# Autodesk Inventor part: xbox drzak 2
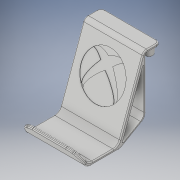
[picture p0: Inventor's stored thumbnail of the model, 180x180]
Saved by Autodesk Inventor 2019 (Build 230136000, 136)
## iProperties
Created: 2022-08
Part Number: xbox drzak 2
Material: Generico
Document SubType Name: Modeling
Designer: holat
Density: 1 g/cm^3
Appearance: Default
Author: holat
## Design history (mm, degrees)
sketch "Náčrt1"
  geometry: L1 (0, 0)-(0, -30); L2 (0, -30)-(70, -55.478); L3 (70, -55.478)-(70, -72.478); L4 (0, 0)-(12.99, 7.5)
  constraints: 8 end point, 1 parallel, 1 vertical
  dimensions: "d0" = 30 distance of L1.start L1.end; "d16" = 17 distance of L2.end L3.end; "d17" = 110 deg angle of L3 L2; "d18" = 120 deg angle of L1 L4; "d26" = 15 distance of L1.start L4.end; "d39" = 70 distance between parallel lines of L1 L3
feature "VysunutíDoPlochy1" sketch "Náčrt1" dims "d1" = 60, "d2" = 0
feature "Zesílit1" dims "d3" = 3, "d4" = 3
sketch "Náčrt2"
  geometry: L1 (0, 0)-(0, 14.899) reference; L2 (60, 14.899)-(60, 0) reference; L3 (0, 14.899)-(60, 14.899) reference; C1 r 4.5 at (54, 5.899); C2 r 4.5 at (6, 5.899); 1 further point
  constraints: 2 centre point
  dimensions: "d5" = 9 diameter of C1; "d6" = 9 diameter of C2 (= d5); "d7" = 48 distance of C2.centre C1.centre; "d10" = 6 distance from line of L2 C1.centre; "d11" = 6 distance from line of L1 C2.centre; "d15" = 9 distance from line of C1.centre L3
extrude "Vysunutí1" join sketch "Náčrt2" distance "d12" = 8; taper "d13" = 0 deg
sketch "Náčrt4"
  geometry: L1 (17, 3)-(42.478, -67) reference; L2 (0, 3)-(17, 3) reference; L3 (0, 3)-(0, 0) reference; L4 (0, 0)-(14.899, 0) reference; L5 (14.899, 0)-(40.377, -70) reference; L6 (40.377, -70)-(74.21, -70) reference; L7 (74.21, -70)-(82.576, -55.51) reference; L8 (79.978, -54.01)-(82.576, -55.51) reference; L9 (72.478, -67)-(79.978, -54.01) reference; L10 (42.478, -67)-(72.478, -67) reference; L11 (14.899, 0)-(14.899, -55.29); L12 (14.899, -55.29)-(40.377, -70); 1 further point
  constraints: 4 end point, 1 vertical
  dimensions: "d40" = 30 deg angle of L6 L12
feature "VysunutíDoPlochy2" sketch "Náčrt4" dims "d28" = 60, "d29" = 0
feature "Zesílit2" dims "d30" = 2, "d31" = 3
fillet "Zaoblení3" dims "d32" = 7, "d141" = 4.75
fillet "Zaoblení6" dims "d38" = 0.5
node "Pracovní rovina1"
sketch "Náčrt5"
  geometry: L1 (59, 0)-(-1, 0) reference; L2 (-1, 66.265)-(59, 66.265) reference; L3 (21.485, 31.235)-(21.485, 34.122); L4 (21.485, 34.122)-(23.985, 35.565); L5 (23.985, 35.565)-(26.485, 34.122); L6 (26.485, 34.122)-(26.485, 31.235); L7 (26.485, 31.235)-(23.985, 29.792); L8 (23.985, 29.792)-(21.485, 31.235); L9 (23.985, 36.143)-(26.985, 34.411); L10 (26.985, 34.411)-(26.985, 30.947); L11 (26.985, 30.947)-(23.985, 29.214); L12 (23.985, 29.214)-(20.985, 30.947); L13 (20.985, 30.947)-(20.985, 34.411); L14 (20.985, 34.411)-(23.985, 36.143); L15 (29.485, 39.318)-(29.485, 36.431); L16 (29.985, 39.607)-(29.985, 36.143); L17 (29.485, 36.431)-(26.985, 34.988); L18 (29.985, 36.143)-(26.985, 34.411); L19 (24.485, 39.318)-(26.985, 40.761); L20 (23.985, 39.607)-(26.985, 41.339); L21 (24.485, 36.431)-(24.485, 39.318); L22 (23.985, 36.143)-(23.985, 39.607); L23 (26.985, 34.988)-(24.485, 36.431); L24 (26.985, 34.411)-(23.985, 36.143); L25 (26.985, 40.761)-(29.485, 39.318); L26 (26.985, 41.339)-(29.985, 39.607); L27 (32.985, 34.411)-(32.985, 30.947); L28 (26.985, 24.018)-(23.985, 25.75); L29 (32.485, 34.122)-(32.485, 31.235); L30 (32.485, 31.235)-(29.985, 29.792); L31 (32.985, 30.947)-(29.985, 29.214); L32 (27.485, 34.122)-(29.985, 35.565); L33 (29.985, 29.214)-(26.985, 30.947); L34 (26.985, 30.947)-(29.985, 29.214); L35 (26.985, 34.411)-(29.985, 36.143); L36 (29.485, 28.926)-(29.485, 26.039); L37 (29.985, 29.214)-(29.985, 25.75); L38 (29.485, 26.039)-(26.985, 24.596); L39 (24.485, 26.039)-(24.485, 28.926); L40 (29.985, 25.75)-(26.985, 24.018); L41 (23.985, 25.75)-(23.985, 29.214); L42 (29.985, 29.792)-(27.485, 31.235); L43 (27.485, 31.235)-(27.485, 34.122); L44 (26.985, 30.947)-(26.985, 34.411); L45 (23.985, 29.214)-(26.985, 30.947); L46 (26.985, 30.369)-(29.485, 28.926); L47 (24.485, 28.926)-(26.985, 30.369); L48 (29.985, 35.565)-(32.485, 34.122); L49 (29.985, 36.143)-(32.985, 34.411); L50 (26.985, 24.596)-(24.485, 26.039); L51 (41.485, 39.318)-(41.485, 36.431); L52 (41.485, 36.431)-(38.985, 34.988); L53 (36.485, 39.318)-(38.985, 40.761); L54 (38.985, 34.411)-(35.985, 36.143); L55 (35.985, 36.143)-(38.985, 34.411); L56 (35.985, 39.607)-(38.985, 41.339); L57 (38.985, 34.988)-(36.485, 36.431); L58 (36.485, 36.431)-(36.485, 39.318); L59 (35.985, 39.607)-(35.985, 36.143); L60 (35.985, 36.143)-(35.985, 39.607); L61 (38.985, 40.761)-(41.485, 39.318); L62 (32.985, 40.761)-(35.485, 39.318); L63 (35.985, 40.184)-(33.485, 41.627); L64 (32.985, 34.411)-(35.985, 36.143)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; 65 further points
  constraints: 768 end point, 32 coincident, 832 other
  dimensions: "d41" = 5 distance between parallel lines of L6 L3; "d42" = 0.5 distance between parallel lines of L5 L9; "d45" = 5 distance between parallel lines of L15 L21; "d46" = 0.5 distance between parallel lines of L25 L26; "d47" = 5 distance between parallel lines of L36 L39; "d48" = 0.5 distance between parallel lines of L46 L34; "d49" = 5 distance between parallel lines of L29 L43; "d50" = 0.5 distance between parallel lines of L48 L49; "d51" = 5 distance between parallel lines of L90 L85; "d52" = 0.5 distance between parallel lines of L62 L91; "d53" = 5 distance between parallel lines of L94 L82; "d54" = 0.5 distance between parallel lines of L83 L88; "d55" = 5 distance between parallel lines of L77 L76; "d56" = 0.5 distance between parallel lines of L75 L55; "d57" = 5 distance between parallel lines of L51 L58; "d58" = 0.5 distance between parallel lines of L61 L87; "d59" = 5 distance between parallel lines of L150 L157; "d60" = 0.5 distance between parallel lines of L145 L151; "d61" = 5 distance between parallel lines of L109 L114; "d62" = 0.5 distance between parallel lines of L113 L112; "d63" = 5 distance between parallel lines of L102 L153; "d64" = 0.5 distance between parallel lines of L103 L101; "d65" = 5 distance between parallel lines of L174 L175; "d66" = 0.5 distance between parallel lines of L180 L168; "d67" = 5 distance between parallel lines of L171 L165; "d68" = 0.5 distance between parallel lines of L131 L170; "d69" = 5 distance between parallel lines of L190 L182; "d70" = 0.5 distance between parallel lines of L183 L192; "d71" = 5 distance between parallel lines of L122 L121; "d72" = 0.5 distance between parallel lines of L120 L193; "d73" = 5 distance between parallel lines of L130 L136; "d74" = 0.5 distance between parallel lines of L173 L140; "d75" = 5 distance between parallel lines of L365 L363; "d76" = 0.5 distance between parallel lines of L318 L348; "d77" = 5 distance between parallel lines of L368 L376; "d78" = 0.5 distance between parallel lines of L340 L373; "d79" = 5 distance between parallel lines of L383 L293; "d80" = 0.5 distance between parallel lines of L382 L384; "d81" = 5 distance between parallel lines of L354 L353; "d82" = 0.5 distance between parallel lines of L336 L346; "d83" = 5 distance between parallel lines of L351 L343; "d84" = 0.5 distance between parallel lines of L366 L317; "d85" = 5 distance between parallel lines of L324 L370; "d86" = 0.5 distance between parallel lines of L327 L321; "d87" = 5 distance between parallel lines of L247 L355; "d88" = 0.5 distance between parallel lines of L297 L309; "d89" = 5 distance between parallel lines of L302 L303; "d90" = 0.5 distance between parallel lines of L329 L306; "d91" = 5 distance between parallel lines of L213 L265; "d92" = 0.5 distance between parallel lines of L218 L220; "d93" = 5 distance between parallel lines of L226 L229; "d94" = 0.5 distance between parallel lines of L228 L227; "d95" = 5 distance between parallel lines of L259 L267; "d96" = 0.5 distance between parallel lines of L224 L225; "d97" = 5 distance between parallel lines of L195 L210; "d98" = 0.5 distance between parallel lines of L239 L276; "d99" = 5 distance between parallel lines of L277 L275; "d100" = 0.5 distance between parallel lines of L250 L278; "d101" = 5 distance between parallel lines of L249 L255; "d102" = 0.5 distance between parallel lines of L257 L299; "d103" = 5 distance between parallel lines of L203 L196; "d104" = 0.5 distance between parallel lines of L204 L207; "d105" = 5 distance between parallel lines of L281 L238; "d106" = 0.5 distance between parallel lines of L296 L282
  node "Promítnutá smyčka3"
extrude "Vysunutí2" cut sketch "Náčrt5" distance "d43" = 1; taper "d44" = 0 deg
extrude "Vysunutí3" cut sketch "Náčrt5" distance "d107" = 1; taper "d108" = 0 deg
extrude "Vysunutí4" cut sketch "Náčrt5" distance "d109" = 1; taper "d110" = 0 deg
extrude "Vysunutí5" cut sketch "Náčrt5" distance "d111" = 2; taper "d112" = 0 deg
extrude "Vysunutí7" cut sketch "Náčrt5" distance "d115" = 0.5; taper "d116" = 0 deg
feature "PlochaZešikmení1" dims angle "d117" = 5 deg
feature "PlochaZešikmení2" dims angle "d118" = 5 deg
chamfer "Zkosení4" distance "d119" = 10; stored, may be unused: second distance "d120" = 2, angle "d121" = 30 deg
chamfer "Zkosení5" distance "d122" = 10; stored, may be unused: second distance "d123" = 2, angle "d124" = 30 deg
fillet "Zaoblení7" dims "d134" = 1
fillet "Zaoblení8" dims "d135" = 4.25
fillet "Zaoblení9" dims "d136" = 11.75
fillet "Zaoblení10" dims "d137" = 1
fillet "Zaoblení11" dims "d138" = 1
fillet "Zaoblení12" dims "d142" = 0.75
fillet "Zaoblení13" dims "d143" = 0.75
sketch "Náčrt11"
  geometry: L1 (-20.071, 58.337)-(78.229, 58.337); L2 (78.229, 58.337)-(78.229, -19.894); L3 (78.229, -19.894)-(-20.071, -19.894); L4 (-20.071, -19.894)-(-20.071, 58.337); L5 (29, 64.627)-(29, 10.112); L6 (29, 52.465)-(26.703, 53.712); L7 (26.703, 53.712)-(23.913, 55.149); L8 (23.913, 55.149)-(20.187, 56.049); L9 (20.187, 56.049)-(18.054, 55.766); L10 (18.054, 55.766)-(17.026, 55.598); L11 (13.468, 52.726)-(14.154, 52.857); L12 (14.154, 52.857)-(15.05, 52.689); L13 (15.05, 52.689)-(16.952, 51.916); L14 (16.952, 51.916)-(18.575, 50.726); L15 (18.575, 50.726)-(20.641, 48.963); L16 (20.641, 48.963)-(22.05, 47.63); L17 (22.05, 47.63)-(22.904, 46.832); L18 (22.904, 46.832)-(20.776, 44.144); L19 (20.776, 44.144)-(18.212, 40.554); L20 (18.212, 40.554)-(15.935, 37.001); L21 (15.935, 37.001)-(13.884, 33.308); L22 (13.884, 33.308)-(12.378, 29.983); L23 (12.378, 29.983)-(11.733, 28.175); L24 (11.733, 28.175)-(11.395, 26.773); L25 (11.395, 26.773)-(11.297, 25.164); L26 (11.297, 25.164)-(11.331, 24.199); L27 (11.331, 24.199)-(11.508, 23.506); L28 (29, 41.265)-(26.934, 39.607); L29 (26.934, 39.607)-(24.224, 37.257); L30 (24.224, 37.257)-(21.766, 34.835); L31 (21.766, 34.835)-(18.798, 31.288); L32 (18.798, 31.288)-(16.586, 28.645); L33 (16.586, 28.645)-(15.35, 26.366); L34 (15.35, 26.366)-(14.191, 24.384); L35 (14.191, 24.384)-(13.959, 23.28); L36 (13.959, 23.28)-(13.787, 22.632); L37 (13.787, 22.632)-(13.787, 21.515); L38 (13.787, 21.515)-(13.959, 21.007); L39 (13.959, 21.007)-(14.288, 20.503); L40 (44.116, 33.308)-(45.622, 29.983); L41 (35.096, 46.832)-(37.224, 44.144); L42 (37.224, 44.144)-(39.788, 40.554); L43 (39.788, 40.554)-(42.065, 37.001); L44 (42.065, 37.001)-(44.116, 33.308); L45 (45.622, 29.983)-(46.267, 28.175); L46 (46.267, 28.175)-(46.605, 26.773); L47 (46.605, 26.773)-(46.703, 25.164); L48 (46.703, 25.164)-(46.669, 24.199); L49 (46.669, 24.199)-(46.492, 23.506); L50 (39.202, 31.288)-(41.414, 28.645); L51 (29, 41.265)-(31.066, 39.607); L52 (31.066, 39.607)-(33.776, 37.257); L53 (33.776, 37.257)-(36.234, 34.835); L54 (36.234, 34.835)-(39.202, 31.288); L55 (41.414, 28.645)-(42.65, 26.366); L56 (42.65, 26.366)-(43.809, 24.384); L57 (43.809, 24.384)-(44.041, 23.28); L58 (44.041, 23.28)-(44.213, 22.632); L59 (44.213, 22.632)-(44.213, 21.515); L60 (44.213, 21.515)-(44.041, 21.007); L61 (44.041, 21.007)-(43.712, 20.503); L62 (29, 52.465)-(31.297, 53.712); L63 (31.297, 53.712)-(34.087, 55.149); L64 (34.087, 55.149)-(37.813, 56.049)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; A1 r 22.174 centre (29.103, 37.001) between (29, 59.176) and (29, 14.827); A2 r 22.174 centre (28.897, 37.001) between (29, 14.827) and (29, 59.176); 1 further point; 1 other entity
  constraints: 12 point on circle, 10 end point, 2 centre point, 2 parallel, 2 vertical, 1 horizontal, 1 perpendicular, 26 other
  dimensions: "d284" = 60 distance between parallel lines of L78 L79 (derived); "d285" = 30 distance from line of L78 L28.start; "d286" = 30.079 distance of L82.end L81.end; "d287" = 24.28223 distance of L81.end L80.end
  node "Obrázek4"
  node "Promítnutá smyčka4"
extrude "Vysunutí8" cut sketch "Náčrt11" distance "d280" = 0.5; taper "d281" = 0 deg
extrude "Vysunutí9" cut sketch "Náčrt11" distance "d282" = 1; taper "d283" = 0 deg
node "Těleso1"
node "Povrch1"
node "Promítnutá smyčka2"
node "Povrch2"
